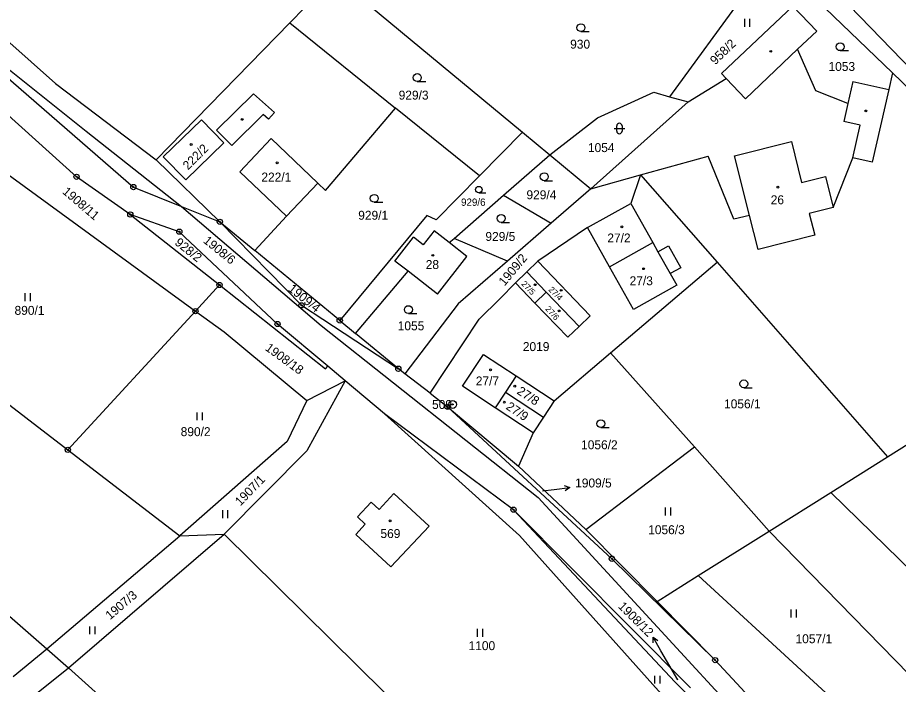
# Model space of a CAD drawing. Extents: x -445050 to -440454, y -1134563 to -1129741.
# Drawn here: x -441230.1 to -441062.5, y -1131481.2 to -1131354.4 of the extents above; entities that cross this region are included whole.
import ezdxf

# ---------------------------------------------------------------- set-up
doc = ezdxf.new("R2010")
doc.units = 0
for name, color, linetype in [('Vrstva 1', 7, 'Continuous'), ('Vrstva 16', 7, 'Continuous'), ('Vrstva 17', 7, 'Continuous'), ('Vrstva 18', 7, 'Continuous'), ('Vrstva 19', 7, 'Continuous'), ('Vrstva 24', 7, 'Continuous'), ('Vrstva 25', 7, 'Continuous'), ('Vrstva 3', 7, 'Continuous'), ('Vrstva 37', 7, 'Continuous'), ('Vrstva 4', 7, 'Continuous')]:
    doc.layers.add(name, color=color, linetype=linetype)

msp = doc.modelspace()

# ---------------------------------------------------------------- linework, layer by layer
at = {"layer": 'Vrstva 1'}
for p, q in [((-441169.7, -1131346.6), (-441134, -1131376.2)), ((-441142.18, -1131384.5), (-441158.2, -1131371.6)), ((-441134, -1131376.2), (-441142.18, -1131384.5)), ((-441134, -1131376.2), (-441128.84, -1131380.48)), ((-441142.18, -1131384.5), (-441150.43, -1131392.87)), ((-441152.22, -1131392.03), (-441168.79, -1131412)), ((-441150.43, -1131392.87), (-441152.22, -1131392.03)), ((-441168.79, -1131412), (-441184.94, -1131398.72)), ((-441168.79, -1131412), (-441165.78, -1131414.48))]:
    msp.add_line(p, q, dxfattribs=at)
for points in [[(-441277.34, -1131318.41), (-441222.87, -1131366.94)], [(-441169.7, -1131346.6), (-441178.3, -1131355.41)], [(-441091.78, -1131349.88), (-441106.04, -1131369.44)], [(-441079.69, -1131349.43), (-441063.64, -1131364.9)], [(-441096.16, -1131365.05), (-441082.6, -1131352.19)], [(-441082.6, -1131352.19), (-441078.07, -1131356.96)], [(-441035.59, -1131389.55), (-441071.86, -1131352.09)], [(-441203.73, -1131381.46), (-441178.3, -1131355.41)], [(-441178.3, -1131355.41), (-441158.2, -1131371.6)], [(-441078.07, -1131356.96), (-441081.71, -1131360.41)], [(-441238.19, -1131360.45), (-441208.04, -1131386.63)], [(-441236.71, -1131360.26), (-441217.04, -1131375.99)], [(-441078.23, -1131368.34), (-441081.71, -1131360.41)], [(-441063.64, -1131364.9), (-441064.37, -1131368.1)], [(-441063.64, -1131364.9), (-441037.08, -1131390.51)], [(-441218.85, -1131384.68), (-441240.32, -1131365.34)], [(-441102.5, -1131370.43), (-441095.31, -1131365.95)], [(-441095.31, -1131365.95), (-441096.16, -1131365.05)], [(-441071.17, -1131366.54), (-441072.13, -1131370.73)], [(-441071.17, -1131366.54), (-441064.37, -1131368.1)], [(-441222.87, -1131366.94), (-441203.73, -1131381.46)], [(-441072.13, -1131370.73), (-441078.23, -1131368.34)], [(-441064.37, -1131368.1), (-441067.52, -1131381.91)], [(-441119.77, -1131373.45), (-441109.07, -1131368.59)], [(-441109.07, -1131368.59), (-441106.04, -1131369.44)], [(-441106.04, -1131369.44), (-441102.5, -1131370.43)], [(-441171.49, -1131387.26), (-441158.2, -1131371.6)], [(-441102.5, -1131370.43), (-441121.02, -1131386.96)], [(-441202.35, -1131380.89), (-441195.11, -1131373.84)], [(-441195.11, -1131373.84), (-441190.86, -1131378.19)], [(-441128.84, -1131380.48), (-441119.77, -1131373.45)], [(-441244.34, -1131375.16), (-441196.23, -1131410.23)], [(-441217.04, -1131375.99), (-441198.88, -1131390.31)], [(-441190.86, -1131378.19), (-441198.08, -1131385.25)], [(-441203.73, -1131381.46), (-441191.59, -1131393.24)], [(-441198.08, -1131385.25), (-441202.35, -1131380.89)], [(-441137.63, -1131388.17), (-441128.84, -1131380.48)], [(-441128.84, -1131380.48), (-441121.02, -1131386.96)], [(-441111.55, -1131384.32), (-441098.73, -1131380.74)], [(-441093.83, -1131392.73), (-441098.73, -1131380.74)], [(-441074.93, -1131390.54), (-441071.19, -1131381.08)], [(-441067.52, -1131381.91), (-441071.19, -1131381.08)], [(-441208.62, -1131391.85), (-441218.85, -1131384.68)], [(-441121.02, -1131386.96), (-441111.55, -1131384.32)], [(-441111.55, -1131384.32), (-441113.41, -1131389.74)], [(-441111.55, -1131384.32), (-441097.01, -1131400.94)], [(-441208.04, -1131386.63), (-441198.88, -1131390.31)], [(-441172.97, -1131385.89), (-441178.93, -1131392.19)], [(-441172.97, -1131385.89), (-441171.49, -1131387.26)], [(-441147.05, -1131396.42), (-441137.63, -1131388.17)], [(-441137.63, -1131388.17), (-441128.56, -1131393.5)], [(-441121.02, -1131386.96), (-441128.56, -1131393.5)], [(-441121.65, -1131394.35), (-441113.41, -1131389.74)], [(-441113.41, -1131389.74), (-441109.24, -1131397.2)], [(-441198.88, -1131390.31), (-441191.59, -1131393.24)], [(-441198.88, -1131390.31), (-441172.29, -1131412.94)], [(-441074.93, -1131390.54), (-441079.47, -1131391.67)], [(-441079.47, -1131391.67), (-441078.45, -1131395.78)], [(-441208.62, -1131391.85), (-441191.65, -1131405.26)], [(-441199.3, -1131395.12), (-441208.62, -1131391.85)], [(-441191.59, -1131393.24), (-441184.94, -1131398.72)], [(-441191.59, -1131393.24), (-441176.06, -1131409.13)], [(-441178.93, -1131392.19), (-441184.94, -1131398.72)], [(-441090.82, -1131392.03), (-441093.83, -1131392.73)], [(-441089.18, -1131398.5), (-441090.82, -1131392.03)], [(-441180.61, -1131412.69), (-441199.3, -1131395.12)], [(-441150.83, -1131394.97), (-441152.91, -1131397.61)], [(-441147.95, -1131397.21), (-441150.83, -1131394.97)], [(-441128.56, -1131393.5), (-441136.87, -1131400.71)], [(-441121.65, -1131394.35), (-441131.09, -1131400.76)], [(-441117.46, -1131401.8), (-441121.65, -1131394.35)], [(-441158.29, -1131400.71), (-441154.76, -1131396.19)], [(-441152.91, -1131397.61), (-441154.76, -1131396.19)], [(-441147.95, -1131397.21), (-441147.05, -1131396.42)], [(-441136.87, -1131400.71), (-441147.05, -1131396.42)], [(-441078.45, -1131395.78), (-441089.18, -1131398.5)], [(-441144.6, -1131399.82), (-441147.95, -1131397.21)], [(-441117.46, -1131401.8), (-441109.24, -1131397.2)], [(-441109.24, -1131397.2), (-441108.26, -1131398.96)], [(-441108.26, -1131398.96), (-441106.24, -1131397.84)], [(-441106.24, -1131397.84), (-441103.94, -1131401.98)], [(-441268.47, -1131399.74), (-441220.51, -1131436.62)], [(-441150.18, -1131407), (-441144.6, -1131399.82)], [(-441155.79, -1131402.65), (-441158.29, -1131400.71)], [(-441136.87, -1131400.71), (-441146.27, -1131408.87)], [(-441133.22, -1131402.78), (-441131.09, -1131400.76)], [(-441131.09, -1131400.76), (-441121.17, -1131411.11)], [(-441112.94, -1131409.91), (-441117.46, -1131401.8)], [(-441117.28, -1131418.2), (-441097.01, -1131400.94)], [(-441097.01, -1131400.94), (-441064.63, -1131437.98)], [(-441165.78, -1131414.48), (-441155.79, -1131402.65)], [(-441150.18, -1131407), (-441155.79, -1131402.65)], [(-441135.36, -1131404.84), (-441133.22, -1131402.78)], [(-441133.22, -1131402.78), (-441129.54, -1131406.6)], [(-441103.94, -1131401.98), (-441105.96, -1131403.1)], [(-441105.96, -1131403.1), (-441104.7, -1131405.3)], [(-441135.36, -1131404.84), (-441138.36, -1131407.91)], [(-441131.7, -1131408.69), (-441135.36, -1131404.84)], [(-441196.23, -1131410.23), (-441191.65, -1131405.26)], [(-441191.65, -1131405.26), (-441171.47, -1131421.21)], [(-441129.54, -1131406.6), (-441131.7, -1131408.69)], [(-441129.54, -1131406.6), (-441123.25, -1131413.13)], [(-441104.7, -1131405.3), (-441112.94, -1131409.91)], [(-441142.26, -1131411.79), (-441138.36, -1131407.91)], [(-441220.51, -1131436.62), (-441196.23, -1131410.23)], [(-441196.23, -1131410.23), (-441190.79, -1131414.19)], [(-441176.06, -1131409.13), (-441157.64, -1131421.19)], [(-441146.27, -1131408.87), (-441156.41, -1131422.14)], [(-441125.43, -1131415.2), (-441131.7, -1131408.69)], [(-441151.61, -1131425.87), (-441142.26, -1131411.79)], [(-441121.17, -1131411.11), (-441123.25, -1131413.13)], [(-441171.05, -1131420.72), (-441180.61, -1131412.69)], [(-441172.29, -1131412.94), (-441131.06, -1131445.66)], [(-441123.25, -1131413.13), (-441125.43, -1131415.2)], [(-441190.79, -1131414.19), (-441175.07, -1131427.26)], [(-441157.64, -1131421.19), (-441165.78, -1131414.48)], [(-441145.41, -1131424.54), (-441141.42, -1131418.49)], [(-441141.42, -1131418.49), (-441135.23, -1131422.57)], [(-441128.01, -1131427.33), (-441117.28, -1131418.2)], [(-441117.28, -1131418.2), (-441101.31, -1131436.03)], [(-441171.47, -1131421.21), (-441171.05, -1131420.72)], [(-441167.76, -1131423.48), (-441171.05, -1131420.72)], [(-441156.41, -1131422.14), (-441157.64, -1131421.19)], [(-441175.07, -1131427.26), (-441167.76, -1131423.48)], [(-441167.76, -1131423.48), (-441175.03, -1131436.83)], [(-441160.29, -1131429.76), (-441167.76, -1131423.48)], [(-441151.61, -1131425.87), (-441156.41, -1131422.14)], [(-441135.23, -1131422.57), (-441137.28, -1131425.68)], [(-441135.23, -1131422.57), (-441128.01, -1131427.33)], [(-441139.22, -1131428.62), (-441145.41, -1131424.54)], [(-441151.61, -1131425.87), (-441148.31, -1131428.43)], [(-441137.28, -1131425.68), (-441139.22, -1131428.62)], [(-441137.28, -1131425.68), (-441130.06, -1131430.43)], [(-441175.07, -1131427.26), (-441178.79, -1131435.01)], [(-441148.31, -1131428.43), (-441117.04, -1131457.34)], [(-441148.31, -1131428.43), (-441134.81, -1131439.71)], [(-441131.99, -1131433.37), (-441139.22, -1131428.62)], [(-441128.01, -1131427.33), (-441130.06, -1131430.43)], [(-441135.73, -1131448.01), (-441160.29, -1131429.76)], [(-441160.29, -1131429.76), (-441134.57, -1131452.95)], [(-441130.06, -1131430.43), (-441131.99, -1131433.37)], [(-441064.63, -1131437.98), (-441054.01, -1131431.31)], [(-441131.99, -1131433.37), (-441134.81, -1131439.71)], [(-441178.79, -1131435.01), (-441199.19, -1131453.01)], [(-441220.51, -1131436.62), (-441199.19, -1131453.01)], [(-441175.03, -1131436.83), (-441190.74, -1131452.67)], [(-441121.96, -1131451.75), (-441101.31, -1131436.03)], [(-441101.31, -1131436.03), (-441087.13, -1131452.1)], [(-441075.41, -1131444.74), (-441064.63, -1131437.98)], [(-441134.81, -1131439.71), (-441121.96, -1131451.75)], [(-441161.3, -1131447.99), (-441158.47, -1131444.92)], [(-441158.47, -1131444.92), (-441151.8, -1131451.16)], [(-441087.13, -1131452.1), (-441075.41, -1131444.74)], [(-441075.41, -1131444.74), (-441007.7, -1131510.75)], [(-441165.4, -1131449.36), (-441162.79, -1131446.58)], [(-441162.79, -1131446.58), (-441161.3, -1131447.99)], [(-441131.06, -1131445.66), (-441068.85, -1131513.28)], [(-441102.09, -1131481.89), (-441135.73, -1131448.01)], [(-441135.73, -1131448.01), (-441104.96, -1131480.83)], [(-441252.93, -1131449.71), (-441224.51, -1131474.49)], [(-441163.93, -1131450.76), (-441165.4, -1131449.36)], [(-441165.7, -1131452.72), (-441163.93, -1131450.76)], [(-441151.8, -1131451.16), (-441159.07, -1131458.91)], [(-441121.96, -1131451.75), (-441108.41, -1131465.46)], [(-441100.6, -1131460.56), (-441087.13, -1131452.1)], [(-441087.13, -1131452.1), (-441060.47, -1131479.37)], [(-441224.51, -1131474.49), (-441199.19, -1131453.01)], [(-441220.39, -1131478.08), (-441190.74, -1131452.67)], [(-441199.19, -1131453.01), (-441190.74, -1131452.67)], [(-441190.74, -1131452.67), (-441124.82, -1131517.82)], [(-441159.07, -1131458.91), (-441165.7, -1131452.72)], [(-441134.57, -1131452.95), (-441104.92, -1131486.07)], [(-441117.04, -1131457.34), (-441097.37, -1131476.63)], [(-441108.41, -1131465.46), (-441100.6, -1131460.56)], [(-441100.6, -1131460.56), (-441061.42, -1131496.56)], [(-441108.41, -1131465.46), (-441097.37, -1131476.63)], [(-441230.87, -1131479.76), (-441224.51, -1131474.49)], [(-441224.51, -1131474.49), (-441220.39, -1131478.08)], [(-441097.37, -1131476.63), (-441052.64, -1131524.89)], [(-441226.44, -1131482.95), (-441220.39, -1131478.08)], [(-441220.39, -1131478.08), (-441154.11, -1131537.76)], [(-441104.96, -1131480.83), (-441091.47, -1131494.51)]]:
    msp.add_lwpolyline(points, dxfattribs=at)
at = {"layer": 'Vrstva 16'}
for p, q in [((-441127.99, -1131444.15), (-441125.01, -1131443.78)), ((-441107.7, -1131474.85), (-441109.2, -1131472.25))]:
    msp.add_line(p, q, dxfattribs=at)
for points in [[(-441126.07, -1131443.4), (-441125.01, -1131443.78), (-441125.94, -1131444.4)], [(-441130.25, -1131444.44), (-441127.99, -1131444.15)], [(-441109.14, -1131473.37), (-441109.2, -1131472.25), (-441108.27, -1131472.87)], [(-441104.48, -1131480.4), (-441107.7, -1131474.85)]]:
    msp.add_lwpolyline(points, dxfattribs=at)
at = {"layer": 'Vrstva 24'}
for centre, radius in [((-441218.85, -1131384.68), 0.5), ((-441218.85, -1131384.68), 0.1), ((-441208.04, -1131386.63), 0.5), ((-441208.04, -1131386.63), 0.1), ((-441208.62, -1131391.85), 0.5), ((-441208.62, -1131391.85), 0.1), ((-441191.59, -1131393.24), 0.5), ((-441191.59, -1131393.24), 0.1), ((-441199.3, -1131395.12), 0.5), ((-441199.3, -1131395.12), 0.1), ((-441191.65, -1131405.26), 0.5), ((-441191.65, -1131405.26), 0.1), ((-441196.23, -1131410.23), 0.5), ((-441196.23, -1131410.23), 0.1), ((-441176.06, -1131409.13), 0.5), ((-441176.06, -1131409.13), 0.1), ((-441168.79, -1131412), 0.5), ((-441168.79, -1131412), 0.1), ((-441180.61, -1131412.69), 0.5), ((-441180.61, -1131412.69), 0.1), ((-441157.64, -1131421.19), 0.5), ((-441157.64, -1131421.19), 0.1), ((-441148.31, -1131428.43), 0.5), ((-441148.31, -1131428.43), 0.1), ((-441147.31, -1131427.99), 0.75), ((-441147.31, -1131427.99), 0.1), ((-441220.51, -1131436.62), 0.5), ((-441220.51, -1131436.62), 0.1), ((-441135.73, -1131448.01), 0.5), ((-441135.73, -1131448.01), 0.1), ((-441117.04, -1131457.34), 0.5), ((-441117.04, -1131457.34), 0.1), ((-441097.37, -1131476.63), 0.5), ((-441097.37, -1131476.63), 0.1)]:
    msp.add_circle(centre, radius, dxfattribs=at)
at = {"layer": 'Vrstva 25'}
for p, q in [((-441091.76, -1131356.12), (-441091.76, -1131354.62)), ((-441090.76, -1131356.12), (-441090.76, -1131354.62)), ((-441122.92, -1131357.06), (-441121.32, -1131357.06)), ((-441073.6, -1131360.68), (-441072, -1131360.68)), ((-441154.04, -1131366.55), (-441152.44, -1131366.55)), ((-441116.09, -1131375.99), (-441116.09, -1131374.99)), ((-441115.09, -1131374.99), (-441115.09, -1131375.99)), ((-441116.59, -1131375.49), (-441114.59, -1131375.49)), ((-441129.89, -1131385.42), (-441128.29, -1131385.42)), ((-441142.32, -1131387.74), (-441141.01, -1131387.74)), ((-441162.22, -1131389.53), (-441160.62, -1131389.53)), ((-441138.08, -1131393.35), (-441136.48, -1131393.35)), ((-441228.59, -1131408.31), (-441228.59, -1131406.81)), ((-441227.59, -1131408.31), (-441227.59, -1131406.81)), ((-441155.72, -1131410.7), (-441154.12, -1131410.7)), ((-441091.93, -1131424.82), (-441090.33, -1131424.82)), ((-441195.88, -1131431.01), (-441195.88, -1131429.51)), ((-441194.88, -1131431.01), (-441194.88, -1131429.51)), ((-441119.12, -1131432.4), (-441117.52, -1131432.4)), ((-441191.04, -1131449.63), (-441191.04, -1131448.13)), ((-441190.04, -1131449.63), (-441190.04, -1131448.13)), ((-441106.81, -1131449.1), (-441106.81, -1131447.6)), ((-441105.81, -1131449.1), (-441105.81, -1131447.6)), ((-441082.92, -1131468.51), (-441082.92, -1131467.01)), ((-441081.92, -1131468.51), (-441081.92, -1131467.01)), ((-441216.32, -1131471.71), (-441216.32, -1131470.21)), ((-441215.32, -1131471.71), (-441215.32, -1131470.21)), ((-441142.58, -1131472.17), (-441142.58, -1131470.67)), ((-441141.58, -1131472.17), (-441141.58, -1131470.67)), ((-441108.87, -1131481.1), (-441108.87, -1131479.6)), ((-441107.87, -1131481.1), (-441107.87, -1131479.6))]:
    msp.add_line(p, q, dxfattribs=at)
for centre, radius in [((-441122.92, -1131356.31), 0.75), ((-441073.6, -1131359.93), 0.75), ((-441086.81, -1131360.81), 0.175), ((-441154.04, -1131365.8), 0.75), ((-441068.72, -1131372.15), 0.175), ((-441187.35, -1131373.75), 0.175), ((-441197.06, -1131378.52), 0.175), ((-441180.7, -1131382.01), 0.175), ((-441129.89, -1131384.67), 0.75), ((-441142.32, -1131387.12), 0.615), ((-441085.44, -1131386.65), 0.175), ((-441162.22, -1131388.78), 0.75), ((-441138.08, -1131392.6), 0.75), ((-441115.11, -1131394.19), 0.175), ((-441151.09, -1131399.62), 0.175), ((-441110.99, -1131402.16), 0.175), ((-441131.6, -1131405.21), 0.175), ((-441126.67, -1131406.28), 0.175), ((-441155.72, -1131409.95), 0.75), ((-441127.05, -1131410.2), 0.175), ((-441140.09, -1131421.39), 0.175), ((-441091.93, -1131424.07), 0.75), ((-441135.5, -1131424.52), 0.175), ((-441137.48, -1131427.55), 0.175), ((-441119.12, -1131431.65), 0.75), ((-441159.22, -1131450.14), 0.175)]:
    msp.add_circle(centre, radius, dxfattribs=at)
for centre, start, end in [((-441115.59, -1131374.99), 0, 180), ((-441115.59, -1131375.99), 180, 0)]:
    msp.add_arc(centre, 0.5, start, end, dxfattribs=at)
at = {"layer": 'Vrstva 3'}
for points in [[(-441202.35, -1131380.89), (-441195.11, -1131373.84)], [(-441195.11, -1131373.84), (-441190.86, -1131378.19)], [(-441190.86, -1131378.19), (-441198.08, -1131385.25)], [(-441187.81, -1131383.72), (-441181.8, -1131377.42)], [(-441181.8, -1131377.42), (-441172.97, -1131385.89)], [(-441093.68, -1131380.67), (-441082.87, -1131377.95)], [(-441082.87, -1131377.95), (-441080.93, -1131385.77)], [(-441198.08, -1131385.25), (-441202.35, -1131380.89)], [(-441090.82, -1131392.03), (-441093.68, -1131380.67)], [(-441178.93, -1131392.19), (-441187.81, -1131383.72)], [(-441080.93, -1131385.77), (-441076.41, -1131384.64)], [(-441076.41, -1131384.64), (-441074.93, -1131390.54)], [(-441172.97, -1131385.89), (-441178.93, -1131392.19)], [(-441121.65, -1131394.35), (-441113.41, -1131389.74)], [(-441113.41, -1131389.74), (-441109.24, -1131397.2)], [(-441074.93, -1131390.54), (-441079.47, -1131391.67)], [(-441079.47, -1131391.67), (-441078.45, -1131395.78)], [(-441089.18, -1131398.5), (-441090.82, -1131392.03)], [(-441150.83, -1131394.97), (-441152.91, -1131397.61)], [(-441147.95, -1131397.21), (-441150.83, -1131394.97)], [(-441117.46, -1131401.8), (-441121.65, -1131394.35)], [(-441158.29, -1131400.71), (-441154.76, -1131396.19)], [(-441152.91, -1131397.61), (-441154.76, -1131396.19)], [(-441078.45, -1131395.78), (-441089.18, -1131398.5)], [(-441144.6, -1131399.82), (-441147.95, -1131397.21)], [(-441117.46, -1131401.8), (-441109.24, -1131397.2)], [(-441117.46, -1131401.8), (-441109.24, -1131397.2)], [(-441109.24, -1131397.2), (-441108.26, -1131398.96)], [(-441150.18, -1131407), (-441144.6, -1131399.82)], [(-441108.26, -1131398.96), (-441105.96, -1131403.1)], [(-441155.79, -1131402.65), (-441158.29, -1131400.71)], [(-441133.22, -1131402.78), (-441131.09, -1131400.76)], [(-441131.09, -1131400.76), (-441121.17, -1131411.11)], [(-441112.94, -1131409.91), (-441117.46, -1131401.8)], [(-441150.18, -1131407), (-441155.79, -1131402.65)], [(-441135.36, -1131404.84), (-441133.22, -1131402.78)], [(-441133.22, -1131402.78), (-441129.54, -1131406.6)], [(-441133.22, -1131402.78), (-441129.54, -1131406.6)], [(-441105.96, -1131403.1), (-441104.7, -1131405.3)], [(-441131.7, -1131408.69), (-441135.36, -1131404.84)], [(-441129.54, -1131406.6), (-441131.7, -1131408.69)], [(-441129.54, -1131406.6), (-441131.7, -1131408.69)], [(-441129.54, -1131406.6), (-441123.25, -1131413.13)], [(-441129.54, -1131406.6), (-441123.25, -1131413.13)], [(-441104.7, -1131405.3), (-441112.94, -1131409.91)], [(-441125.43, -1131415.2), (-441131.7, -1131408.69)], [(-441121.17, -1131411.11), (-441123.25, -1131413.13)], [(-441123.25, -1131413.13), (-441125.43, -1131415.2)], [(-441145.41, -1131424.54), (-441141.42, -1131418.49)], [(-441141.42, -1131418.49), (-441135.23, -1131422.57)], [(-441135.23, -1131422.57), (-441137.28, -1131425.68)], [(-441135.23, -1131422.57), (-441137.28, -1131425.68)], [(-441135.23, -1131422.57), (-441128.01, -1131427.33)], [(-441139.22, -1131428.62), (-441145.41, -1131424.54)], [(-441137.28, -1131425.68), (-441139.22, -1131428.62)], [(-441137.28, -1131425.68), (-441139.22, -1131428.62)], [(-441137.28, -1131425.68), (-441130.06, -1131430.43)], [(-441137.28, -1131425.68), (-441130.06, -1131430.43)], [(-441131.99, -1131433.37), (-441139.22, -1131428.62)], [(-441128.01, -1131427.33), (-441130.06, -1131430.43)], [(-441130.06, -1131430.43), (-441131.99, -1131433.37)], [(-441161.3, -1131447.99), (-441158.47, -1131444.92)], [(-441158.47, -1131444.92), (-441151.8, -1131451.16)], [(-441165.4, -1131449.36), (-441162.79, -1131446.58)], [(-441162.79, -1131446.58), (-441161.3, -1131447.99)], [(-441163.93, -1131450.76), (-441165.4, -1131449.36)], [(-441165.7, -1131452.72), (-441163.93, -1131450.76)], [(-441151.8, -1131451.16), (-441159.07, -1131458.91)], [(-441159.07, -1131458.91), (-441165.7, -1131452.72)]]:
    msp.add_lwpolyline(points, dxfattribs=at)
at = {"layer": 'Vrstva 37'}
for centre in [(-441197.06, -1131378.52), (-441180.7, -1131382.01), (-441085.44, -1131386.65), (-441115.11, -1131394.19), (-441151.09, -1131399.62), (-441110.99, -1131402.16), (-441131.6, -1131405.21), (-441126.67, -1131406.28), (-441127.05, -1131410.2), (-441140.09, -1131421.39), (-441135.5, -1131424.52), (-441137.48, -1131427.55), (-441159.22, -1131450.14)]:
    msp.add_circle(centre, 0.175, dxfattribs=at)
at = {"layer": 'Vrstva 4'}
for points in [[(-441081.71, -1131360.41), (-441091.64, -1131369.82)], [(-441091.64, -1131369.82), (-441095.31, -1131365.95)], [(-441192.2, -1131375.81), (-441185.17, -1131368.87)], [(-441185.17, -1131368.87), (-441181.18, -1131372.42)], [(-441072.13, -1131370.73), (-441072.91, -1131374.15)], [(-441183.34, -1131372.81), (-441189.33, -1131378.72)], [(-441182.33, -1131373.7), (-441183.34, -1131372.81)], [(-441181.18, -1131372.42), (-441182.33, -1131373.7)], [(-441069.78, -1131374.87), (-441072.91, -1131374.15)], [(-441071.19, -1131381.08), (-441069.78, -1131374.87)], [(-441189.33, -1131378.72), (-441192.2, -1131375.81)], [(-441187.81, -1131383.72), (-441181.8, -1131377.42)], [(-441181.8, -1131377.42), (-441172.97, -1131385.89)], [(-441093.68, -1131380.67), (-441082.87, -1131377.95)], [(-441082.87, -1131377.95), (-441080.93, -1131385.77)], [(-441090.82, -1131392.03), (-441093.68, -1131380.67)], [(-441178.93, -1131392.19), (-441187.81, -1131383.72)], [(-441080.93, -1131385.77), (-441076.41, -1131384.64)], [(-441076.41, -1131384.64), (-441074.93, -1131390.54)], [(-441108.26, -1131398.96), (-441105.96, -1131403.1)]]:
    msp.add_lwpolyline(points, dxfattribs=at)

# ---------------------------------------------------------------- texts
at = {"layer": 'Vrstva 16'}
msp.add_text('1909/5', height=1.7, dxfattribs=at).set_placement((-441124.01, -1131443.78))
msp.add_text('1908/12', height=1.7, rotation=315.2401, dxfattribs=at).set_placement((-441115.96, -1131466.54))
at = {"layer": 'Vrstva 17'}
msp.add_text('509', height=1.7, dxfattribs=at).set_placement((-441151.23, -1131428.84))
at = {"layer": 'Vrstva 18'}
for s, height, p in [('930', 1.7, (-441124.96, -1131360.3)), ('1053', 1.7, (-441075.82, -1131364.54)), ('929/3', 1.7, (-441157.58, -1131369.99)), ('1054', 1.7, (-441121.58, -1131379.98)), ('929/4', 1.7, (-441133.27, -1131388.95)), ('929/6', 1.39, (-441145.71, -1131390.2)), ('929/1', 1.7, (-441165.27, -1131392.85)), ('929/5', 1.7, (-441141.08, -1131396.88)), ('890/1', 1.7, (-441230.64, -1131410.94)), ('1055', 1.7, (-441157.76, -1131413.88)), ('2019', 1.7, (-441133.96, -1131417.83)), ('1056/1', 1.7, (-441095.69, -1131428.73)), ('890/2', 1.7, (-441199.04, -1131434.02)), ('1056/2', 1.7, (-441122.88, -1131436.51)), ('1909/5', 0.1, (-441130.47, -1131444.44)), ('1056/3', 1.7, (-441110.12, -1131452.67)), ('1057/1', 1.7, (-441082.09, -1131473.41)), ('1100', 1.7, (-441144.28, -1131474.73)), ('1908/12', 0.1, (-441104.72, -1131480.4))]:
    msp.add_text(s, height=height, dxfattribs=at).set_placement(p)
for s, rotation, p in [('958/2', 43.9371, (-441097.37, -1131363.49)), ('1908/11', 319.3667, (-441221.67, -1131387.71)), ('928/2', 321.2574, (-441200.3, -1131397.45)), ('1908/6', 320.9319, (-441194.88, -1131397.07)), ('1909/2', 50.3586, (-441137.43, -1131405.56)), ('1909/4', 321.057, (-441178.74, -1131406.23)), ('1908/18', 323.9609, (-441183.11, -1131417.55)), ('1907/1', 45.7326, (-441187.69, -1131447.4)), ('1907/3', 40.4127, (-441212.46, -1131469.04))]:
    msp.add_text(s, height=1.7, rotation=rotation, dxfattribs=at).set_placement(p)
at = {"layer": 'Vrstva 19'}
for s, height, rotation, p in [('222/2', 1.7, 45.082, (-441197.63, -1131383.49)), ('27/5', 1.14, 313.9272, (-441134.34, -1131405.14)), ('27/4', 1.14, 315.2894, (-441129.16, -1131406.24)), ('27/6', 1.14, 311.9606, (-441129.77, -1131409.88)), ('27/8', 1.7, 326.7783, (-441135.23, -1131425.85)), ('27/9', 1.7, 326.1798, (-441137.31, -1131428.76))]:
    msp.add_text(s, height=height, rotation=rotation, dxfattribs=at).set_placement(p)
for s, p in [('222/1', (-441183.69, -1131385.58)), ('26', (-441086.81, -1131389.9)), ('27/2', (-441117.89, -1131397.17)), ('28', (-441152.43, -1131402.22)), ('27/3', (-441113.65, -1131405.31)), ('27/7', (-441142.91, -1131424.37)), ('569', (-441161.04, -1131453.4))]:
    msp.add_text(s, height=1.7, dxfattribs=at).set_placement(p)

doc.saveas('drawing.dxf')
